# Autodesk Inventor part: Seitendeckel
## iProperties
Created: 2007-04
Part Number: Seitendeckel
Material: Aluminium, halbhart
Document SubType Name: Sheet Metal
Designer: bh
StanzNr: #
ST: 1,50 mm
Author: bh
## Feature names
1. Spiegeln1 [Mirror]
2. Spiegeln2 [Mirror]
3. Grobblech3
4. Grobblech4
5. Biegung2
6. Grobblech5
7. Biegung3
8. Grobblech6
9. Biegung4
10. Grobblech7
11. Biegung5
12. Ecke1
13. Ecke2
14. Ecke3
15. Ecke4
